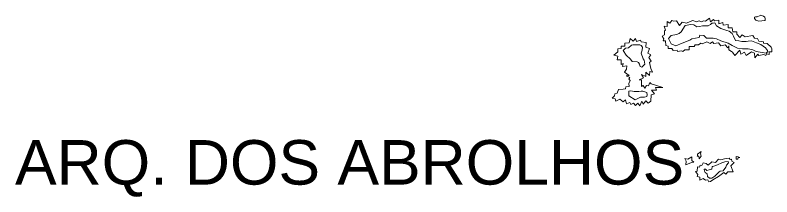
# Model space of a CAD drawing. Extents: x 47169 to 972804, y 7447977 to 9608469.
# Drawn here: x 521607 to 532674, y 8011546 to 8014198 of the extents above; entities that cross this region are included whole.
import ezdxf

# ---------------------------------------------------------------- set-up
doc = ezdxf.new("R2010")
doc.units = 0
doc.header["$LTSCALE"] = 270
doc.layers.add('1', color=7, linetype='Continuous', lineweight=13)
doc.layers.add('3', color=7, linetype='Continuous')

msp = doc.modelspace()

# ---------------------------------------------------------------- linework, layer by layer
at = {"layer": '1'}
for points in [[(532483.8, 8014109.8), (532441.5, 8014124.3), (532418.2, 8014147.5), (532418.3, 8014167.5), (532433.1, 8014173), (532456.4, 8014172.9), (532502, 8014192.8), (532514.7, 8014198.3), (532550.7, 8014182.7), (532568.7, 8014170.5), (532576, 8014145.1), (532576, 8014124), (532568.6, 8014119.6)], [(532419.5, 8013644.1), (532374, 8013665.2), (532295.6, 8013608.9), (532272.4, 8013659.9), (532219.4, 8013629), (532203.6, 8013687.6), (532134.6, 8013611.4), (532099.8, 8013660.1), (532083.9, 8013667.9), (532045.8, 8013691.2), (532045.9, 8013748.8), (532031.1, 8013723.3), (531993, 8013764.3), (531927.3, 8013752.2), (531891.4, 8013795.5), (531825.7, 8013785.6), (531804.6, 8013811.1), (531771.7, 8013785.7), (531720.9, 8013811.2), (531655.2, 8013780.4), (531635.1, 8013788.1), (531599.1, 8013765), (531550.4, 8013765), (531535.5, 8013742.9), (531464.6, 8013743), (531464.5, 8013694.4), (531401, 8013694.5), (531372.3, 8013669.1), (531350.1, 8013676.8), (531296.1, 8013667), (531288.7, 8013686.9), (531230.5, 8013681.5), (531212.5, 8013712.5), (531159.6, 8013712.5), (531156.4, 8013745.7), (531123.6, 8013755.8), (531118.4, 8013824.4), (531085.6, 8013824.4), (531093.1, 8013852.1), (531070.9, 8013890.8), (531103.8, 8013912.9), (531103.8, 8013969.3), (531116.6, 8013981.5), (531100.8, 8014035.7), (531144.2, 8014032.3), (531144.3, 8014104.2), (531182.4, 8014083.2), (531213.2, 8014121.8), (531240.7, 8014111.8), (531278.8, 8014114), (531325.3, 8014045.3), (531363.5, 8014096.1), (531427, 8014082.8), (531477.9, 8014108.1), (531516, 8014118), (531572.1, 8014100.2), (531610.2, 8014115.7), (531643.1, 8014100.1), (531673.8, 8014117.8), (531703.4, 8014111.1), (531759.6, 8014154.2), (531777.5, 8014099.9), (531821, 8014133), (531835.8, 8014113.1), (531897.2, 8014122.9), (531897.1, 8014072), (531955.4, 8014089.7), (531962.8, 8014054.2), (532034.8, 8014064.1), (532033.6, 8014013.2), (532095.1, 8014010.9), (532102.4, 8013954.4), (532163.8, 8013954.3), (532163.8, 8013922.2), (532207.1, 8013873.5), (532237.8, 8013911.1), (532283.3, 8013881.1), (532397.7, 8013903.1), (532419.9, 8013863.2), (532463.3, 8013859.8), (532481.2, 8013819.9), (532552.2, 8013808.8), (532552.1, 8013788.9), (532602.9, 8013784.3), (532664.3, 8013730), (532673.8, 8013707.9), (532671.6, 8013664.7), (532635.6, 8013661.5), (532633.4, 8013626.1), (532594.4, 8013635.5), (532587.8, 8013608.4), (532557.2, 8013626.2), (532483, 8013608.6), (532470.3, 8013628.6), (532424.7, 8013577.7)], [(532442.9, 8013669.5), (532394.2, 8013690.6), (532326.5, 8013708.5), (532244.9, 8013708.6), (532172.9, 8013718.7), (532092.5, 8013754.2), (532033.3, 8013789.7), (531929.6, 8013825.3), (531866.1, 8013850.8), (531815.2, 8013860.9), (531715.7, 8013864.3), (531680.8, 8013902), (531619.4, 8013905.4), (531609.8, 8013874.5), (531505, 8013851.4), (531474.2, 8013831.5), (531363, 8013790.8), (531270.8, 8013750), (531202, 8013781.1), (531161.9, 8013855.3), (531202.2, 8013902.8), (531278.5, 8013915.9), (531316.6, 8013931.4), (531345.3, 8013955.7), (531403.6, 8014045.2), (531490.5, 8014062.7), (531533.9, 8014054.9), (531574.1, 8014029.4), (531614.3, 8014031.6), (531660.9, 8014042.6), (531701.2, 8014044.7), (531744.6, 8014044.6), (531775.3, 8014060.1), (531797.6, 8014080), (531813.5, 8014082.1), (531841, 8014085.4), (531866.4, 8014044.4), (531929.8, 8014001.2), (532016.6, 8013975.6), (532051.6, 8013965.6), (532092.8, 8013932.3), (532115, 8013891.4), (532140.3, 8013830.5), (532191.1, 8013822.6), (532234.5, 8013812.6), (532295.9, 8013812.5), (532326.7, 8013820.2), (532377.5, 8013822.3), (532450.5, 8013794.5), (532514, 8013769), (532580.6, 8013722.4), (532610.2, 8013684.8), (532613.3, 8013667), (532590, 8013643.8)], [(531079.2, 8013142.9), (530972.3, 8013143), (530988.1, 8013105.4), (530914, 8013103.3), (530957.3, 8013049), (530908.6, 8013036.9), (530903.2, 8012942.9), (530862.9, 8012915.3), (530830.1, 8012945.2), (530791.9, 8012897.7), (530771.8, 8012940.9), (530743.2, 8012874.6), (530712.5, 8012915.5), (530679.6, 8012880.2), (530652.2, 8012915.6), (530610.8, 8012894.7), (530598.2, 8012923.5), (530547.3, 8012902.5), (530532.6, 8012963.4), (530499.7, 8012933.6), (530451.1, 8012971.3), (530389.6, 8012941.5), (530382.2, 8012976.9), (530336.7, 8012984.7), (530372.8, 8013020.1), (530377.1, 8013047.7), (530413.1, 8013057.6), (530431.2, 8013111.8), (530500, 8013116.1), (530532.8, 8013121.6), (530538.2, 8013151.5), (530589, 8013154.7), (530581.7, 8013202.3), (530601.8, 8013243.2), (530581.8, 8013263.2), (530598.7, 8013286.4), (530543.7, 8013311.9), (530589.3, 8013319.6), (530520.5, 8013368.4), (530548.1, 8013411.5), (530551.4, 8013456.8), (530487.8, 8013447), (530500.6, 8013494.5), (530469.9, 8013476.9), (530467.8, 8013545.5), (530411.7, 8013545.5), (530421.3, 8013602), (530361, 8013612), (530421.4, 8013662.8), (530421.5, 8013706), (530468.1, 8013711.4), (530468.2, 8013744.6), (530521.1, 8013746.7), (530523.3, 8013789.9), (530584.7, 8013792), (530602.8, 8013856.2), (530643, 8013817.4), (530681.2, 8013856), (530691.7, 8013815.1), (530752.1, 8013834.9), (530760.5, 8013809.4), (530833.6, 8013797.1), (530828.2, 8013733), (530882.1, 8013713), (530858.7, 8013644.4), (530902.1, 8013621.1), (530874.5, 8013581.3), (530909.4, 8013524.9), (530883.9, 8013505), (530901.8, 8013420.9), (530929.2, 8013367.7), (530889, 8013375.5), (530883.6, 8013319.1), (530836.1, 8013362.3), (530830.8, 8013367.9), (530832.8, 8013301.5), (530769.3, 8013331.5), (530794.6, 8013281.6), (530734.2, 8013253), (530769.2, 8013252.9), (530769.1, 8013194.3), (530769, 8013156.6), (530789.2, 8013172.1), (530817.7, 8013131.1), (530840, 8013172), (530868.6, 8013164.2), (530890.9, 8013212.9), (530908.8, 8013197.4)], [(530544.2, 8013613.9), (530500.9, 8013682.6), (530531.6, 8013715.7), (530579.3, 8013723.4), (530620.7, 8013762.1), (530640.8, 8013764.2), (530678.9, 8013764.2), (530742.4, 8013764.1), (530760.4, 8013754.1), (530780.5, 8013733.1), (530775.1, 8013685.5), (530764.5, 8013644.6), (530789.8, 8013560.5), (530807.7, 8013540.5), (530815.1, 8013481.9), (530772.6, 8013441), (530749.4, 8013451), (530738.8, 8013484.2), (530721.9, 8013507.5), (530703.9, 8013515.2), (530633, 8013523.1), (530604.5, 8013556.3)], [(530674.5, 8012963.2), (530583.5, 8013022), (530580.4, 8013062.9), (530580.4, 8013086.1), (530583.6, 8013090.5), (530609, 8013093.8), (530659.8, 8013086), (530692.7, 8013086), (530728.7, 8013085.9), (530763.6, 8013090.3), (530786.9, 8013090.2), (530843, 8013070.2), (530848.2, 8013034.8), (530845, 8013009.4), (530810.1, 8012999.5), (530771.9, 8012999.5), (530750.8, 8012999.6)], [(531611.2, 8012103.1), (531606, 8012140.8), (531580.6, 8012140.8), (531583.8, 8012151.9), (531583.8, 8012169.6), (531642.1, 8012207.1), (531631.5, 8012171.7), (531642, 8012140.7)], [(531502.2, 8012131), (531502.1, 8012075.7), (531532.8, 8012050.2), (531496.8, 8012046.9), (531415.2, 8012011.6), (531422.7, 8012065.8), (531400.5, 8012103.5), (531446.1, 8012097.9)], [(531621.3, 8011787.8), (531621.4, 8011834.3), (531583.3, 8011841), (531590.8, 8011874.1), (531558, 8011917.4), (531580.2, 8011920.6), (531587.8, 8011983.7), (531613.2, 8011978.1), (531623.8, 8012009.1), (531651.3, 8012001.3), (531669.4, 8012044.4), (531710.7, 8012032.2), (531740.3, 8012008.9), (531796.5, 8012057.5), (531850.4, 8012049.6), (531892.9, 8012097.2), (531928.8, 8012087.1), (531979.7, 8012102.5), (532048.6, 8012112.4), (532063.3, 8012089.1), (532084.5, 8012096.8), (532086.6, 8012064.7), (532122.6, 8012045.9), (532073.8, 8012000.6), (532109.6, 8011912), (532030.2, 8011912.2), (531999.5, 8011879), (531972, 8011899), (531895.6, 8011840.5), (531811.9, 8011793), (531778, 8011769.8), (531752.6, 8011764.4), (531737.8, 8011793.1), (531701.8, 8011789.9), (531666.9, 8011813.2)], [(532183, 8012129.9), (532203.2, 8012122.1), (532183, 8012119.9), (532177.7, 8012094.5), (532150.2, 8012096.7), (532150.2, 8012107.8), (532150.2, 8012133.2)], [(531839.5, 8011848.3), (531794, 8011820.7), (531761.1, 8011820.8), (531730.5, 8011840.7), (531727.3, 8011879.5), (531699.9, 8011902.7), (531687.2, 8011920.5), (531681.9, 8011950.3), (531702.1, 8011950.3), (531723.2, 8011932.6), (531756, 8011940.3), (531794.2, 8011948), (531799.5, 8011988.9), (531812.2, 8011991.1), (531877.9, 8012014.2), (531943.6, 8012044), (531987.1, 8012059.4), (532033.6, 8012061.5), (532037.8, 8012041.6), (532010.2, 8012008.5), (531999.6, 8011977.5), (531961.4, 8011926.7), (531918, 8011920.1), (531901, 8011909)]]:
    msp.add_lwpolyline(points, close=True, dxfattribs=at)

# ---------------------------------------------------------------- texts
at = {"layer": '3', "width": 1.05}
msp.add_text('ARQ. DOS ABROLHOS', height=649.9, dxfattribs=at).set_placement((521605, 8011724.5))

doc.saveas('drawing.dxf')
